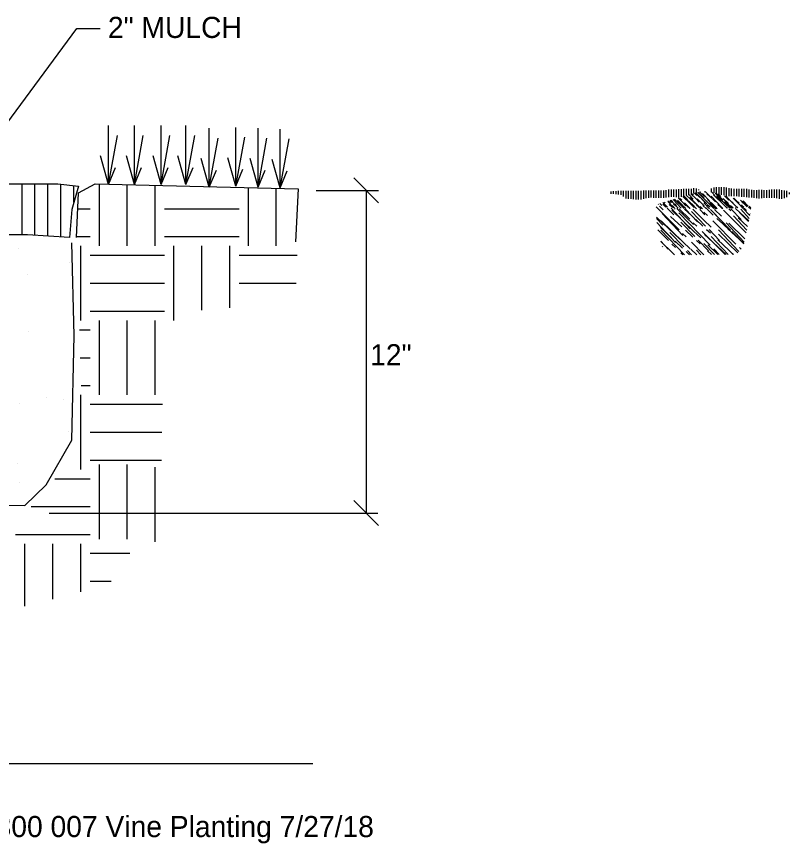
# Model space of a CAD drawing. Extents: x 10082 to 10257, y 10014 to 10069.
# Drawn here: x 10142.62 to 10168.25, y 10014.39 to 10041.82 of the extents above; entities that cross this region are included whole.
import ezdxf

# ---------------------------------------------------------------- set-up
doc = ezdxf.new("R2010")
doc.units = 0
for name, color, linetype in [('Default', 7, 'Continuous'), ('G-ANNO-CELL', 7, 'Continuous'), ('G-ANNO-TEXT', 7, 'Continuous'), ('G-DETL-LINE', 7, 'Continuous'), ('G-DETL-OTLN', 7, 'Continuous'), ('G-DETL-PATT', 7, 'Continuous'), ('G-DETL-TEXT', 7, 'Continuous')]:
    doc.layers.add(name, color=color, linetype=linetype)

# ---------------------------------------------------------------- blocks, each defined once
blk = doc.blocks.new('_X3')
at = {"layer": 'Default'}
for p, q in [((2.0243, 1.27594), (2.00019, 1.30005)), ((2.00379, 1.30073), (2.00766, 1.29713)), ((2.01867, 1.29176), (2.01176, 1.29892)), ((2.01595, 1.29868), (2.03605, 1.27712)), ((2.01961, 1.29846), (2.0203, 1.29775)), ((2.0396, 1.28172), (2.02178, 1.29833)), ((2.03552, 1.28717), (2.02452, 1.29817)), ((2.03015, 1.29786), (2.03784, 1.29069)), ((2.03121, 1.29782), (2.04379, 1.28434)), ((2.05044, 1.28611), (2.0386, 1.29755)), ((2.07661, 1.29795), (2.07884, 1.29587)), ((2.08969, 1.28678), (2.07879, 1.29807)), ((2.09766, 1.28545), (2.08382, 1.29836)), ((2.08918, 1.29773), (2.09823, 1.28803)), ((2.09892, 1.29113), (2.09126, 1.29879)), ((2.09277, 1.29887), (2.09513, 1.29644)), ((2.09741, 1.30026), (2.09986, 1.29797)), ((2.09986, 1.2991), (2.09818, 1.30084)), ((2.02516, 1.26624), (2.00034, 1.28938)), ((2.00665, 1.29312), (2.02831, 1.2699)), ((2.0154, 1.28991), (2.02701, 1.27908)), ((2.03941, 1.27469), (2.01657, 1.29675)), ((2.02398, 1.29394), (2.05706, 1.25968)), ((2.05215, 1.27995), (2.03745, 1.29517)), ((2.04621, 1.29726), (2.05153, 1.29156)), ((2.05423, 1.29091), (2.05049, 1.29465)), ((2.05403, 1.2972), (2.05396, 1.29726)), ((2.05407, 1.29726), (2.06028, 1.29147)), ((2.06357, 1.29098), (2.05744, 1.29733)), ((2.05749, 1.29733), (2.07609, 1.27806)), ((2.06908, 1.29018), (2.0616, 1.29741)), ((2.09486, 1.27273), (2.07107, 1.29652)), ((2.08144, 1.29051), (2.09547, 1.27547)), ((2.09752, 1.28479), (2.08772, 1.29425)), ((2.0988, 1.29263), (2.09916, 1.29226)), ((2.00726, 1.28073), (2.00053, 1.2877)), ((2.00097, 1.2837), (2.02057, 1.26268)), ((2.02839, 1.26327), (2.00555, 1.28533)), ((2.04073, 1.26892), (2.02603, 1.28415)), ((2.04301, 1.27969), (2.03927, 1.28343)), ((2.04171, 1.28708), (2.04945, 1.27986)), ((2.05805, 1.27876), (2.05044, 1.28611)), ((2.08417, 1.26098), (2.05985, 1.2853)), ((2.06415, 1.28787), (2.06802, 1.28426)), ((2.09237, 1.26144), (2.06564, 1.28637)), ((2.07827, 1.27575), (2.06725, 1.28717)), ((2.0737, 1.28329), (2.0927, 1.26292)), ((2.09351, 1.26659), (2.0767, 1.28283)), ((2.08658, 1.28865), (2.09636, 1.27953)), ((2.01307, 1.26472), (2.00182, 1.27597)), ((2.00457, 1.2783), (2.01619, 1.26747)), ((2.00495, 1.27556), (2.02992, 1.2497)), ((2.02931, 1.25789), (2.01461, 1.27312)), ((2.03178, 1.26846), (2.02804, 1.2722)), ((2.03088, 1.27547), (2.03862, 1.26825)), ((2.04703, 1.26734), (2.03941, 1.27469)), ((2.07286, 1.24983), (2.04862, 1.27407)), ((2.05332, 1.27626), (2.05719, 1.27265)), ((2.06685, 1.26472), (2.05583, 1.27614)), ((2.08597, 1.2518), (2.06567, 1.27141)), ((2.06596, 1.27608), (2.08736, 1.25313)), ((2.07576, 1.27704), (2.08737, 1.26621)), ((2.07977, 1.27425), (2.09233, 1.26125)), ((2.00496, 1.2639), (2.01283, 1.25547)), ((2.01736, 1.25186), (2.005, 1.26379)), ((2.02006, 1.26386), (2.0278, 1.25664)), ((2.036, 1.25592), (2.02839, 1.26327)), ((2.05048, 1.24976), (2.0374, 1.26285)), ((2.04249, 1.26465), (2.04636, 1.26104)), ((2.05543, 1.25369), (2.04441, 1.26511)), ((2.07378, 1.24984), (2.05121, 1.27089)), ((2.05822, 1.26886), (2.07596, 1.24984)), ((2.06493, 1.26543), (2.07654, 1.2546)), ((2.09232, 1.2612), (2.08562, 1.26814)), ((2.09124, 1.2626), (2.09239, 1.26153)), ((2.00731, 1.25782), (2.00686, 1.25828)), ((2.02056, 1.25724), (2.01682, 1.26098)), ((2.0372, 1.24972), (2.03299, 1.25409)), ((2.04285, 1.24974), (2.03677, 1.25541)), ((2.04274, 1.25442), (2.0471, 1.24975)), ((2.05048, 1.26164), (2.06153, 1.2498)), ((2.06518, 1.24981), (2.05464, 1.25999)), ((2.06074, 1.25587), (2.06659, 1.24981)), ((2.08121, 1.24986), (2.07421, 1.25711)), ((2.08973, 1.25541), (2.08791, 1.25724)), ((2.01962, 1.24967), (2.01736, 1.25186)), ((2.0281, 1.24969), (2.02617, 1.25162)), ((2.03167, 1.25304), (2.03522, 1.24972)), ((2.0541, 1.25382), (2.05842, 1.24979)), ((2.08041, 1.25099), (2.08162, 1.24986))]:
    blk.add_line(p, q, dxfattribs=at)
blk = doc.blocks.new('_X2')
at = {"layer": 'Default'}
for p, q in [((2.05846, 1.31543), (2.05846, 1.31955)), ((2.0611, 1.31488), (2.0611, 1.32049)), ((2.06375, 1.31432), (2.06375, 1.32074)), ((2.0664, 1.31344), (2.0664, 1.32083)), ((2.06904, 1.31275), (2.06904, 1.32091)), ((2.07169, 1.3123), (2.07169, 1.321)), ((2.07433, 1.31186), (2.07433, 1.32052)), ((2.07698, 1.31151), (2.07698, 1.31992)), ((2.07963, 1.31151), (2.07963, 1.31932)), ((2.08227, 1.31151), (2.08227, 1.31896)), ((2.08492, 1.31129), (2.08492, 1.31906)), ((2.08756, 1.31106), (2.08756, 1.31916)), ((2.09021, 1.31083), (2.09021, 1.31926)), ((2.09285, 1.3106), (2.09285, 1.31911)), ((2.0955, 1.31037), (2.0955, 1.31897)), ((2.09815, 1.31014), (2.09815, 1.31856)), ((2.10079, 1.30981), (2.10079, 1.318)), ((2.10344, 1.30946), (2.10344, 1.31754)), ((2.10608, 1.30912), (2.10608, 1.31782)), ((2.10873, 1.30878), (2.10873, 1.3181)), ((2.11138, 1.30911), (2.11138, 1.31811)), ((2.11402, 1.30969), (2.11402, 1.3178)), ((2.11667, 1.30976), (2.11667, 1.31753)), ((2.11931, 1.30976), (2.11931, 1.3179)), ((2.12196, 1.30976), (2.12196, 1.31827)), ((2.1246, 1.30969), (2.1246, 1.31857)), ((2.12725, 1.30919), (2.12725, 1.31841)), ((2.1299, 1.30869), (2.1299, 1.31825)), ((2.13254, 1.3086), (2.13254, 1.31784)), ((2.13519, 1.30938), (2.13519, 1.31743)), ((2.13783, 1.31035), (2.13783, 1.31702)), ((2.14048, 1.31352), (2.14048, 1.31514))]:
    blk.add_line(p, q, dxfattribs=at)
blk = doc.blocks.new('_X1')
at = {"layer": 'Default'}
for p, q in [((1.95263, 1.31367), (1.95263, 1.31626)), ((1.95527, 1.31367), (1.95527, 1.31649)), ((1.95792, 1.31347), (1.95792, 1.31671)), ((1.96056, 1.31305), (1.96056, 1.31693)), ((1.96321, 1.31262), (1.96321, 1.31716)), ((1.96585, 1.31087), (1.96585, 1.31717)), ((1.9685, 1.30902), (1.9685, 1.31717)), ((1.97115, 1.30856), (1.97115, 1.31717)), ((1.97379, 1.30841), (1.97379, 1.31709)), ((1.97644, 1.30823), (1.97644, 1.31698)), ((1.97908, 1.30803), (1.97908, 1.31687)), ((1.98173, 1.30783), (1.98173, 1.31697)), ((1.98438, 1.30782), (1.98438, 1.31715)), ((1.98702, 1.30847), (1.98702, 1.31734)), ((1.98967, 1.30912), (1.98967, 1.31751)), ((1.99231, 1.30978), (1.99231, 1.31751)), ((1.99496, 1.30997), (1.99496, 1.31751)), ((1.9976, 1.30972), (1.9976, 1.31751)), ((2.00025, 1.30947), (2.00025, 1.31744)), ((2.0029, 1.30951), (2.0029, 1.31735)), ((2.00554, 1.30962), (2.00554, 1.31726)), ((2.00819, 1.30972), (2.00819, 1.31721)), ((2.01083, 1.30997), (2.01083, 1.31787)), ((2.01348, 1.31029), (2.01348, 1.31853)), ((2.01613, 1.31062), (2.01613, 1.31847)), ((2.01877, 1.31073), (2.01877, 1.31833)), ((2.02142, 1.31041), (2.02142, 1.31836)), ((2.02406, 1.31013), (2.02406, 1.31864)), ((2.02671, 1.31079), (2.02671, 1.31892)), ((2.02935, 1.31146), (2.02935, 1.3192)), ((2.032, 1.31203), (2.032, 1.31914)), ((2.03465, 1.31248), (2.03465, 1.31899)), ((2.03729, 1.31294), (2.03729, 1.3192)), ((2.03994, 1.31413), (2.03994, 1.3197)), ((2.04258, 1.31531), (2.04258, 1.31953)), ((2.04523, 1.31784), (2.04523, 1.31835))]:
    blk.add_line(p, q, dxfattribs=at)
blk = doc.blocks.new('_X0')
at = {"layer": 'Default'}
for p, q in [((0.61524, 0.33277), (0.60719, 0.34054)), ((0.60826, 0.34086), (0.61428, 0.33441)), ((0.61286, 0.33657), (0.60862, 0.34097)), ((0.60864, 0.34098), (0.61177, 0.33773)), ((0.62251, 0.3312), (0.6112, 0.34175)), ((0.61391, 0.34257), (0.61815, 0.33802)), ((0.62075, 0.33848), (0.6159, 0.34317)), ((0.61857, 0.34209), (0.61716, 0.34355)), ((0.61956, 0.34427), (0.62202, 0.34163)), ((0.62004, 0.34441), (0.62524, 0.33956)), ((0.63236, 0.33302), (0.62075, 0.34463)), ((0.62973, 0.33894), (0.62286, 0.34534)), ((0.62313, 0.34501), (0.63967, 0.32788)), ((0.62626, 0.34419), (0.62488, 0.34553)), ((0.62556, 0.34559), (0.62589, 0.34524)), ((0.63007, 0.34051), (0.62626, 0.34419)), ((0.63531, 0.33618), (0.62796, 0.34379)), ((0.62998, 0.346), (0.63065, 0.34537)), ((0.63797, 0.33863), (0.63055, 0.34605)), ((0.63259, 0.34356), (0.63646, 0.33995)), ((0.63698, 0.34111), (0.6478, 0.3295)), ((0.64102, 0.34169), (0.63759, 0.34525)), ((0.65081, 0.33152), (0.63939, 0.34255)), ((0.64132, 0.34421), (0.65167, 0.33311)), ((0.64265, 0.34384), (0.64919, 0.33707)), ((0.6563, 0.32864), (0.64275, 0.34127)), ((0.64837, 0.33408), (0.64286, 0.33979)), ((0.64448, 0.34333), (0.64574, 0.34215)), ((0.64733, 0.3405), (0.64546, 0.34237)), ((0.6511, 0.34149), (0.65554, 0.33672)), ((0.65632, 0.33723), (0.65225, 0.34116)), ((0.65408, 0.33959), (0.65268, 0.34104)), ((0.58147, 0.33228), (0.58106, 0.33267)), ((0.58512, 0.33102), (0.58297, 0.33324)), ((0.58617, 0.33258), (0.5894, 0.32957)), ((0.59106, 0.32942), (0.58625, 0.33423)), ((0.58872, 0.33377), (0.58774, 0.33468)), ((0.58797, 0.33159), (0.58989, 0.32953)), ((0.59409, 0.33316), (0.59152, 0.33582)), ((0.59184, 0.3352), (0.5978, 0.3288)), ((0.59636, 0.32894), (0.59279, 0.33238)), ((0.59365, 0.33646), (0.59545, 0.33478)), ((0.59439, 0.33668), (0.60226, 0.32854)), ((0.59681, 0.33489), (0.59487, 0.33683)), ((0.59835, 0.32875), (0.59593, 0.33125)), ((0.59697, 0.33746), (0.6056, 0.3282)), ((0.59739, 0.33297), (0.59932, 0.33117)), ((0.60866, 0.32809), (0.59848, 0.33792)), ((0.60055, 0.33115), (0.59868, 0.33302)), ((0.60715, 0.33106), (0.60164, 0.33677)), ((0.6104, 0.32802), (0.60175, 0.33609)), ((0.60261, 0.33916), (0.61041, 0.33081)), ((0.6028, 0.33878), (0.60474, 0.33697)), ((0.60617, 0.33676), (0.6043, 0.33863)), ((0.60861, 0.33336), (0.61441, 0.32795)), ((0.61508, 0.32785), (0.60897, 0.33395)), ((0.61361, 0.33582), (0.62147, 0.32769)), ((0.61402, 0.33917), (0.61983, 0.33376)), ((0.62651, 0.32764), (0.61459, 0.33957)), ((0.61904, 0.32909), (0.61524, 0.33277)), ((0.62144, 0.32769), (0.61654, 0.33277)), ((0.62456, 0.3348), (0.62075, 0.33848)), ((0.62176, 0.33195), (0.62563, 0.32834)), ((0.6296, 0.33067), (0.62225, 0.33828)), ((0.62717, 0.33776), (0.63104, 0.33415)), ((0.63204, 0.32758), (0.62836, 0.33113)), ((0.62924, 0.33389), (0.63515, 0.32755)), ((0.63298, 0.33234), (0.63491, 0.33054)), ((0.63311, 0.3375), (0.64219, 0.32776)), ((0.64323, 0.32781), (0.63388, 0.33684)), ((0.6361, 0.32928), (0.63423, 0.33115)), ((0.64174, 0.32774), (0.63553, 0.33353)), ((0.64266, 0.32857), (0.63715, 0.33428)), ((0.63839, 0.33815), (0.64033, 0.33634)), ((0.64171, 0.33489), (0.63984, 0.33676)), ((0.6442, 0.33274), (0.6492, 0.32807)), ((0.64856, 0.32804), (0.64452, 0.33208)), ((0.64961, 0.33854), (0.65542, 0.33313)), ((0.65931, 0.32852), (0.65013, 0.3377)), ((0.65416, 0.32829), (0.65081, 0.33152)), ((0.65102, 0.33517), (0.65753, 0.32844)), ((0.66013, 0.33355), (0.65632, 0.33723)), ((0.65735, 0.33132), (0.66031, 0.32856)), ((0.66465, 0.32865), (0.65776, 0.33579)), ((0.66791, 0.33115), (0.66007, 0.33899)), ((0.66351, 0.33638), (0.661, 0.33873)), ((0.66277, 0.33713), (0.66664, 0.33352)), ((0.66663, 0.33259), (0.67015, 0.32881)), ((0.67082, 0.33369), (0.66778, 0.33684)), ((0.66781, 0.33683), (0.67477, 0.32962)), ((0.66857, 0.33171), (0.67051, 0.32991)), ((0.67149, 0.32894), (0.66932, 0.33097)), ((0.67528, 0.32996), (0.66945, 0.33559)), ((0.67065, 0.33604), (0.67592, 0.33038)), ((0.67476, 0.32961), (0.67266, 0.33179)), ((0.60341, 0.32829), (0.60336, 0.32834)), ((0.62537, 0.33028), (0.62784, 0.32762)), ((0.63259, 0.32758), (0.63144, 0.32876)), ((0.65397, 0.32828), (0.65205, 0.33027)), ((0.66276, 0.32898), (0.66307, 0.32865)), ((0.66521, 0.32865), (0.66394, 0.32988)), ((0.67024, 0.32882), (0.66978, 0.32928))]:
    blk.add_line(p, q, dxfattribs=at)
blk = doc.blocks.new('POINT_DISPLAY')
at = {"layer": 'Default'}
blk.add_line((0, 0), (0, 0), dxfattribs=at)

msp = doc.modelspace()

# ---------------------------------------------------------------- linework, layer by layer
at = {"layer": 'Default'}
for p, q in [((10140.91, 10036.381), (10144.62, 10041.417)), ((10144.62, 10041.417), (10145.398, 10041.417)), ((10154.632, 10035.638), (10153.807, 10036.463)), ((10152.561, 10036.05), (10154.629, 10036.05)), ((10154.22, 10036.05), (10154.22, 10025.35)), ((10154.632, 10024.937), (10153.807, 10025.762)), ((10143.71, 10025.35), (10154.604, 10025.35))]:
    msp.add_line(p, q, dxfattribs=at)
at = {"layer": 'G-ANNO-TEXT'}
for p, q in [((10120.67, 10017.044), (10152.453, 10017.044)), ((10120.67, 10017.044), (10152.453, 10017.044)), ((10122.114, 10017.044), (10151.008, 10017.044)), ((10122.114, 10017.044), (10151.008, 10017.044))]:
    msp.add_line(p, q, dxfattribs=at)
at = {"layer": 'G-DETL-LINE'}
for p, q in [((10145.675, 10036.251), (10145.675, 10038.2)), ((10146.532, 10036.251), (10146.532, 10038.2)), ((10147.415, 10036.251), (10147.415, 10038.2)), ((10148.242, 10036.251), (10148.242, 10038.2)), ((10149.015, 10036.163), (10149.015, 10038.112)), ((10149.894, 10036.191), (10149.894, 10038.14)), ((10150.634, 10036.163), (10150.634, 10038.112)), ((10151.369, 10036.133), (10151.369, 10038.082)), ((10145.675, 10036.251), (10145.971, 10037.876)), ((10146.532, 10036.251), (10146.828, 10037.876)), ((10147.415, 10036.251), (10147.711, 10037.876)), ((10148.242, 10036.251), (10148.537, 10037.876)), ((10149.015, 10036.163), (10149.311, 10037.788)), ((10149.894, 10036.191), (10150.19, 10037.816)), ((10150.634, 10036.163), (10150.929, 10037.788)), ((10151.369, 10036.133), (10151.665, 10037.758)), ((10145.675, 10036.251), (10145.41, 10037.195)), ((10146.532, 10036.251), (10146.266, 10037.195)), ((10147.415, 10036.251), (10147.15, 10037.195)), ((10148.242, 10036.251), (10147.976, 10037.195)), ((10149.015, 10036.163), (10148.75, 10037.108)), ((10149.894, 10036.191), (10149.629, 10037.135)), ((10150.634, 10036.163), (10150.368, 10037.108)), ((10151.369, 10036.133), (10151.104, 10037.077)), ((10145.675, 10036.251), (10145.91, 10036.814)), ((10146.532, 10036.251), (10146.767, 10036.814)), ((10147.415, 10036.251), (10147.65, 10036.814)), ((10148.242, 10036.251), (10148.477, 10036.814)), ((10149.015, 10036.163), (10149.25, 10036.726)), ((10149.894, 10036.191), (10150.13, 10036.753)), ((10150.634, 10036.163), (10150.869, 10036.726)), ((10151.369, 10036.133), (10151.604, 10036.696))]:
    msp.add_line(p, q, dxfattribs=at)
at = {"layer": 'G-DETL-OTLN'}
for points in [[(10140.876, 10036.369), (10141.827, 10036.266), (10143.994, 10036.266), (10144.682, 10036.196), (10144.453, 10035.42), (10144.382, 10034.486), (10142.99, 10034.574), (10141.827, 10034.574), (10140.876, 10034.574)], [(10144.611, 10034.486), (10144.682, 10035.966), (10145.228, 10036.266), (10151.958, 10036.107), (10151.87, 10034.344)], [(10132.402, 10025.6), (10139.273, 10025.671), (10142.902, 10025.6), (10143.607, 10026.288), (10144.453, 10027.769), (10144.541, 10031.242), (10144.455, 10034.311)]]:
    msp.add_lwpolyline(points, dxfattribs=at)
at = {"layer": 'G-DETL-PATT'}
for p, q in [((10142.807, 10034.574), (10142.807, 10036.266)), ((10143.236, 10034.558), (10143.236, 10036.266)), ((10143.666, 10034.531), (10143.666, 10036.266)), ((10144.096, 10034.504), (10144.096, 10036.256)), ((10144.525, 10035.666), (10144.525, 10036.212)), ((10145.371, 10034.209), (10145.371, 10036.263)), ((10146.297, 10034.209), (10146.297, 10036.241)), ((10147.224, 10034.209), (10147.224, 10036.219)), ((10150.311, 10034.209), (10150.311, 10036.146)), ((10151.238, 10034.209), (10151.238, 10036.124)), ((10144.657, 10035.444), (10145.062, 10035.444)), ((10147.532, 10035.444), (10150.003, 10035.444)), ((10144.613, 10034.518), (10145.062, 10034.518)), ((10147.532, 10034.518), (10150.003, 10034.518)), ((10144.753, 10031.739), (10144.753, 10034.209)), ((10147.841, 10031.739), (10147.841, 10034.209)), ((10148.768, 10032.077), (10148.768, 10034.209)), ((10149.694, 10032.16), (10149.694, 10034.209)), ((10142.674, 10034.133), (10142.674, 10034.133)), ((10144.365, 10033.673), (10144.365, 10033.673)), ((10145.062, 10033.9), (10147.532, 10033.9)), ((10150.003, 10033.9), (10151.934, 10033.9)), ((10142.999, 10033.254), (10142.999, 10033.254)), ((10145.062, 10032.974), (10147.532, 10032.974)), ((10150.003, 10032.974), (10151.896, 10032.974)), ((10145.062, 10032.047), (10147.532, 10032.047)), ((10145.371, 10029.268), (10145.371, 10031.739)), ((10146.297, 10029.268), (10146.297, 10031.739)), ((10147.224, 10029.268), (10147.224, 10031.739)), ((10143.022, 10031.36), (10143.022, 10031.36)), ((10144.709, 10031.43), (10145.062, 10031.43)), ((10144.739, 10030.503), (10145.062, 10030.503)), ((10144.769, 10029.577), (10145.062, 10029.577)), ((10144.753, 10026.798), (10144.753, 10029.268)), ((10142.712, 10028.984), (10142.712, 10028.984)), ((10143.605, 10029.197), (10143.605, 10029.197)), ((10144.184, 10029.124), (10144.184, 10029.124)), ((10145.062, 10028.96), (10147.469, 10028.96)), ((10144.337, 10028.041), (10144.337, 10028.041)), ((10145.062, 10028.033), (10147.448, 10028.033)), ((10145.062, 10027.107), (10147.428, 10027.107)), ((10142.658, 10026.999), (10142.658, 10026.999)), ((10145.371, 10024.485), (10145.371, 10026.956)), ((10146.297, 10024.485), (10146.297, 10026.956)), ((10147.224, 10024.4), (10147.224, 10026.871)), ((10142.732, 10026.362), (10142.732, 10026.362)), ((10143.899, 10026.489), (10145.062, 10026.489)), ((10143.112, 10025.563), (10145.062, 10025.563)), ((10142.592, 10024.637), (10145.062, 10024.637)), ((10142.901, 10022.261), (10142.901, 10024.328)), ((10143.827, 10022.498), (10143.827, 10024.328)), ((10144.753, 10022.735), (10144.753, 10024.328)), ((10145.062, 10024.019), (10146.385, 10024.019)), ((10145.062, 10023.093), (10145.766, 10023.093))]:
    msp.add_line(p, q, dxfattribs=at)

# ---------------------------------------------------------------- block references
at = {"layer": 'Default', "xscale": 31.496062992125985, "yscale": 31.496062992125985}
for name, p in [('_X1', (10100.837, 9994.556)), ('_X2', (10100.837, 9994.556)), ('_X0', (10145.594, 10025.119)), ('_X3', (10100.837, 9994.556)), ('POINT_DISPLAY', (10166.894, 10035.483))]:
    msp.add_blockref(name, p, dxfattribs=at)

# ---------------------------------------------------------------- texts
at = {"layer": 'G-ANNO-CELL'}
msp.add_text('MD 329300 007 Vine Planting 7/27/18', height=0.7, dxfattribs=at).set_placement((10138.653, 10014.603))
at = {"layer": 'G-DETL-TEXT'}
for s, p in [('2" MULCH', (10145.655, 10041.107)), ('12"', (10154.351, 10030.25))]:
    msp.add_text(s, height=0.7, dxfattribs=at).set_placement(p)

doc.saveas('drawing.dxf')
